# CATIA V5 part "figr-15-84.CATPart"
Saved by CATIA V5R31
Part number: Part1
Bounding box of the stored display mesh (mm): x 0 to 27, y -46 to 46, z -30 to 30
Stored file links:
  D:\PROJECTS\Project 2021\US EDITION\CATIA V5 6R 2021\Resources\Part Files\c15_catia_v5_6r2021_prt\figr-15-84.CATPart
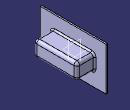
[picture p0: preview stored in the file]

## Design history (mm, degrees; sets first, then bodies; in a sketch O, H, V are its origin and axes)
SheetMetalParameters1: Thickness 2, BendRadius 4, KFactor 0.400515 {= log(min(100,max(20*SheetMetalParameters1.BendRadius,SheetMetalParameters1.Thickness)/SheetMetalParameters1.Thickness))/log(100)/2}, ReliefRadialLength 1, ReliefAxialLength 2, MinimumBendRadius 0
Body1 (main body)
  Sketch1 on yz-plane, origin (0, 0, 0), H (0, 1, 0), V (0, 0, 1)
    line L1 (46, 30) -> (46, -30)
    line L2 (46, -30) -> (-46, -30)
    line L3 (-46, -30) -> (-46, 30)
    line L4 (-46, 30) -> (46, 30)
    vertical: L1 V, L3 V
    horizontal: L2 H, L4 H
    equidistance: L1 L3 O, L2 L4 O
  Wall1: Thickness 2, Profile Sketch1, OffsetValue 0
  Sketch2 on face of Wall1, origin (2, 0, 0), H (0, 1, 0), V (0, 0, 1)
    line L1 (28, 9) -> (28, -9)
    line L2 (28, -9) -> (-28, -9)
    line L3 (-28, -9) -> (-28, 9)
    line L4 (-28, 9) -> (28, 9)
    vertical: L1 V, L3 V
    horizontal: L2 H, L4 H
    equidistance: L1 L3 O, L2 L4 O
  d_Stamp1: NewRoot_AttribNormalisation "No Standard", Stamp_FilletRadius 2, Stamp_IntersectFilletRadius 2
